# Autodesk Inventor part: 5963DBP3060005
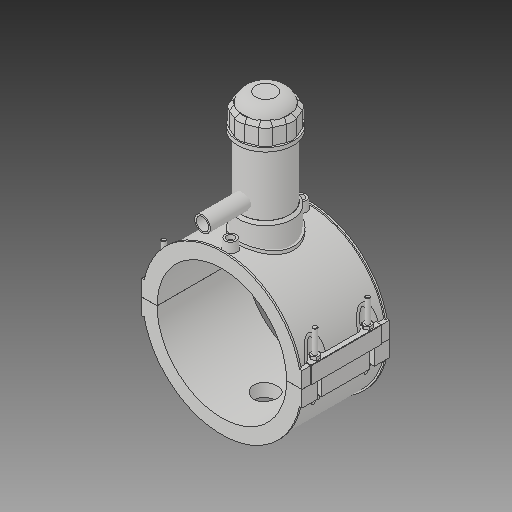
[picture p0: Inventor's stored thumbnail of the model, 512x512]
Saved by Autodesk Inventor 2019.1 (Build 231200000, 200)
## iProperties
Created: 2017-07
Part Number: 5963DBP3060005
Material: Generic
Description: PLASSON TAPPING SADDLE 6''DIPS x 1/2''IPS
Document SubType Name: Modeling
Designer: KIM
Density: 1 g/cm^3
Appearance: Default
Author: KIM
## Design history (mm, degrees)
derived "5963DBP_5963BUP.ipt"
feature "Solid1::5963DBP_5963BUP.ipt"
feature "Solid2::5963DBP_5963BUP.ipt"
feature "Solid3::5963DBP_5963BUP.ipt"
tag "TaggingFeature1"
body "Solid1"
body "Solid2"
body "Solid3"
other parameters: "d_" = 174.5, "B_" = 215.9, "L_" = 118.11, "d_t" = 6, "H_2" = 177.038, "H_1" = 65.024, "d_1" = 21.2, "H_" = 85.09, "d1" = 209.4, "d148" = 2.6175, "d160" = 2.6175, "d169" = 3.4335, "d192" = 7.3248, "d0" = 174.5, "d2" = 215.9, "d3" = 43.625, "d4" = 118.11, "d5" = 0, "d6" = 0.1, "d8" = 0, "d19" = 6, "d20" = 6, "d21" = 70.866, "d23" = 0, "d24" = 35.433, "d26" = 0, "d27" = 3, "d28" = 3, "d29" = 3, "d30" = 58.16667, "d31" = 6, "d32" = 0, "d33" = 0, "d34" = 0.6, "d40" = 108.888, "d41" = 75.035, "d43" = 0, "d45" = 0, "d47" = 175.566, "d70" = 15, "d72" = 0, "d73" = 6, "d75" = 5, "d76" = 0, "d77" = 8.725, "d78" = 117.25, "d79" = 15, "d80" = 47.244, "d82" = 5 deg, "d84" = 4, "d85" = 14, "d86" = 0, "d87" = 3, "d88" = 0, "d89" = 1, "d90" = 1, "d91" = 94.488, "d92" = 0, "d93" = 0.5, "d94" = 91.84211, "d96" = 213.588, "d97" = 2.3622, "d98" = 0, "d120" = 140 deg, "d121" = 24.228, "d122" = 20 deg, "d123" = 418.8, "d124" = 125.64, "d126" = 0, "d143" = 179.735, "d145" = 26.84615, "d149" = 2.6175, "d150" = 29.53077, "d153" = 118.11, "d154" = 0, "d156" = 104.7, "d157" = 160 deg, "d159" = 6.98, "d161" = 2.6175, "d162" = 70.866, "d163" = 0, "d164" = 87.25, "d167" = 17.45, "d168" = 102.14634, "d170" = 3.4335, "d172" = 0, "d173" = 1, "d175" = 87.25, "d176" = 20 deg, "d177" = 12.215, "d178" = 34.9, "d180" = 0, "d183" = 13.96, "d184" = 9.772, "d185" = 38.38575, "d186" = 38.38575, "d187" = 104.7, "d188" = 10.47, "d189" = 12.215, "d190" = 0, "d191" = 157.05, "d193" = 7.3248, "d194" = 4.13385, "d195" = 90 deg, "d197" = 0, "d199" = 0, "d200" = 17.45, "d202" = 0, "d203" = 177.038, "d204" = 71.28325, "d205" = 52.5245, "d206" = 63.77975, "d207" = 132.7785, "d208" = 138.08964, "d209" = 164.64534, "d210" = 64.5301, "d211" = 75.035, "d212" = 60.028, "d213" = 48.9816, "d216" = 0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
